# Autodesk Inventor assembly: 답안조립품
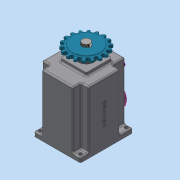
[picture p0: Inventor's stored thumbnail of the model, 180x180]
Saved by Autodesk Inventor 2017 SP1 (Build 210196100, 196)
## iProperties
Part Number: 답안조립품
Material: 일반
Document SubType Name: Assembly
Designer: MRC
Author: MRC
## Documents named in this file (16)
- C:\Users\MRC\Desktop\720212V1005\답안조립품.iam
- C:\Users\MRC\Desktop\720212V1005\본체.ipt
- C:\Users\MRC\Desktop\720212V1005\멈춤나사 M3.ipt
- C:\Users\MRC\Desktop\720212V1005\메인 축.ipt
- C:\Users\MRC\Desktop\720212V1005\베어링 608.ipt
- C:\Users\MRC\Desktop\720212V1005\베어링 6003.ipt
- C:\Users\MRC\Desktop\720212V1005\볼트 M4 x 10.ipt
- C:\Users\MRC\Desktop\720212V1005\부시.ipt
- C:\Users\MRC\Desktop\720212V1005\상부 캡.ipt
- C:\Users\MRC\Desktop\720212V1005\서브 축.ipt
- C:\Users\MRC\Desktop\720212V1005\스프로킷.ipt
- C:\Users\MRC\Desktop\720212V1005\슬라이더.ipt
- C:\Users\MRC\Desktop\720212V1005\오일 실 8 x 22 x 7.ipt
- C:\Users\MRC\Desktop\720212V1005\오일 실 17 x 32 x 8.ipt
- C:\Users\MRC\Desktop\720212V1005\커버.ipt
- C:\Users\MRC\Desktop\720212V1005\키 5 x 5.ipt
